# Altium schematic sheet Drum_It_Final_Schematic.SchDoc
size A; SheetNumber: 1; SheetTotal: 1
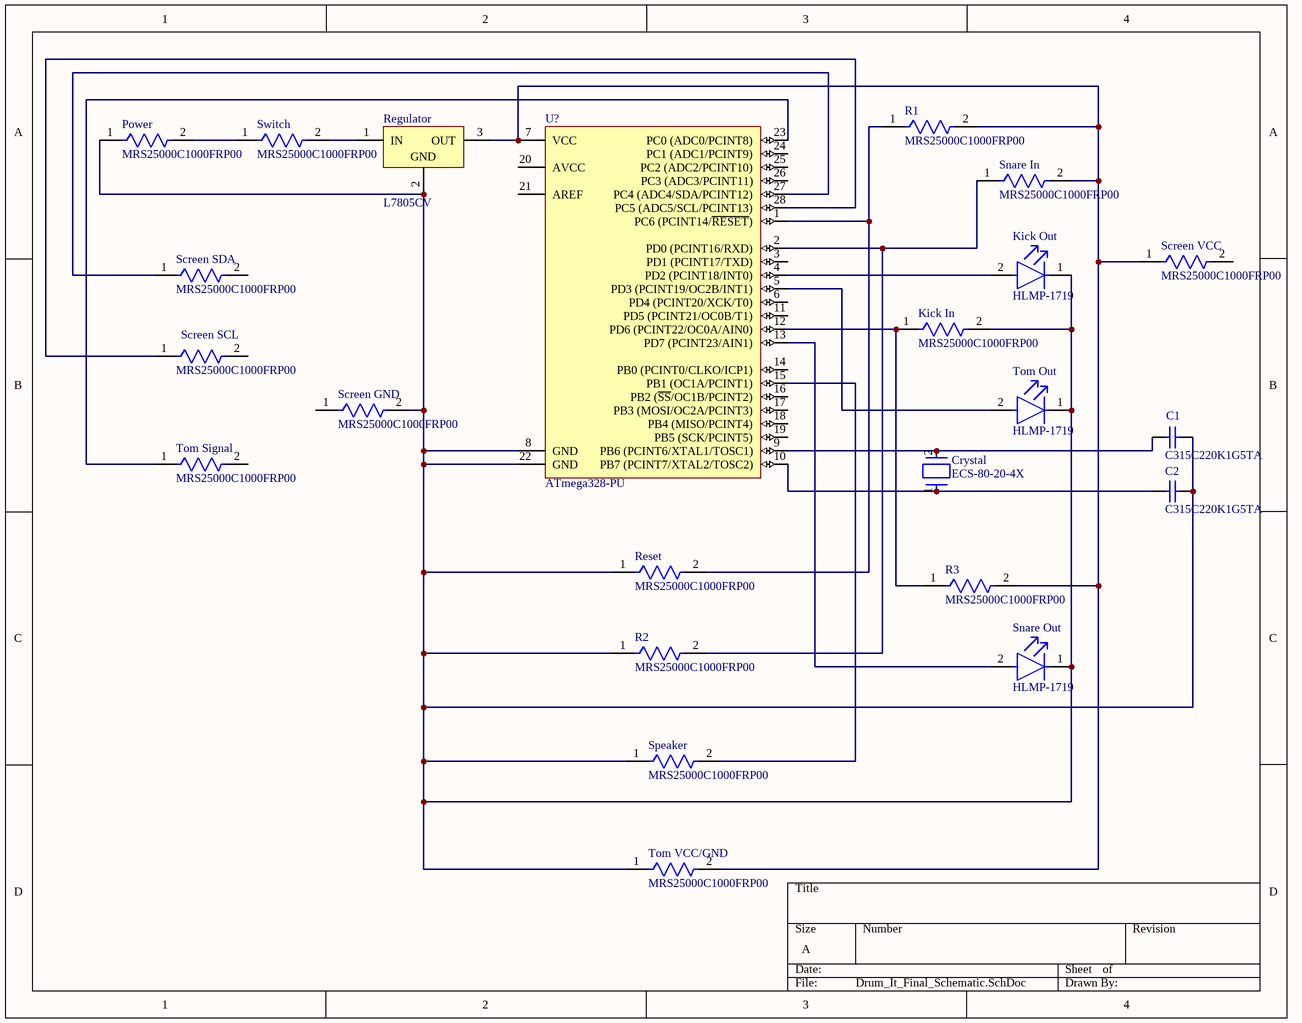
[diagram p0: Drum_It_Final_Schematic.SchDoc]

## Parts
C1  C315C220K1G5TA  [KEMT-C315-THT-2]
C2  C315C220K1G5TA  [KEMT-C315-THT-2]
Crystal  ECS-80-20-4X  [FP-ECS-80-20-4X-MFG]
Kick_In  MRS25000C1000FRP00  [FP-MRS25-MFG]
Kick_Out  HLMP-1719  [FP-HLMP-1719-MFG]
Power  MRS25000C1000FRP00  [FP-MRS25-MFG]
R1  MRS25000C1000FRP00  [FP-MRS25-MFG]
R2  MRS25000C1000FRP00  [FP-MRS25-MFG]
R3  MRS25000C1000FRP00  [FP-MRS25-MFG]
Regulator  L7805CV  [TO220]
Reset  MRS25000C1000FRP00  [FP-MRS25-MFG]
Screen_GND  MRS25000C1000FRP00  [FP-MRS25-MFG]
Screen_SCL  MRS25000C1000FRP00  [FP-MRS25-MFG]
Screen_SDA  MRS25000C1000FRP00  [FP-MRS25-MFG]
Screen_VCC  MRS25000C1000FRP00  [FP-MRS25-MFG]
Snare_In  MRS25000C1000FRP00  [FP-MRS25-MFG]
Snare_Out  HLMP-1719  [FP-HLMP-1719-MFG]
Speaker  MRS25000C1000FRP00  [FP-MRS25-MFG]
Switch  MRS25000C1000FRP00  [FP-MRS25-MFG]
Tom_Out  HLMP-1719  [FP-HLMP-1719-MFG]
Tom_Signal  MRS25000C1000FRP00  [FP-MRS25-MFG]
Tom_VCC/GND  MRS25000C1000FRP00  [FP-MRS25-MFG]
U?  ATmega328-PU  [28P3]

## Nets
NetC1_1: C1.1 Crystal.2 U?.9(PB6_(PCINT6/XTAL1/TOSC1))
NetC1_2: C1.2 C2.2 Kick_In.2 Kick_Out.1(C) Power.1 R2.1 Regulator.2(GND) Reset.1 Screen_GND.2 Snare_Out.1(C) Speaker.1 Tom_Out.1(C) Tom_VCC/GND.1 U?.8(GND) U?.22(GND)
NetC2_1: C2.1 Crystal.1 U?.10(PB7_(PCINT7/XTAL2/TOSC2))
NetKick_In_1: Kick_In.1 R3.1 U?.12(PD6_(PCINT22/OC0A/AIN0))
NetKick_Out_2: Kick_Out.2(A) U?.4(PD2_(PCINT18/INT0))
NetPower_2: Power.2 Switch.1
NetR1_1: R1.1 Reset.2 U?.1(PC6_(PCINT14/~{RESET}))
NetR1_2: R1.2 R3.2 Regulator.3(OUT) Screen_VCC.1 Snare_In.2 Tom_VCC/GND.2 U?.7(VCC)
NetR2_2: R2.2 Snare_In.1 U?.2(PD0_(PCINT16/RXD))
NetRegulator_1: Regulator.1(IN) Switch.2
NetScreen_SCL_1: Screen_SCL.1 U?.28(PC5_(ADC5/SCL/PCINT13))
NetScreen_SDA_1: Screen_SDA.1 U?.27(PC4_(ADC4/SDA/PCINT12))
NetSnare_Out_2: Snare_Out.2(A) U?.13(PD7_(PCINT23/AIN1))
NetSpeaker_2: Speaker.2 U?.15(PB1_(OC1A/PCINT1))
NetTom_Out_2: Tom_Out.2(A) U?.5(PD3_(PCINT19/OC2B/INT1))
NetTom_Signal_1: Tom_Signal.1 U?.23(PC0_(ADC0/PCINT8))

Not connected (* = marked no-connect by the designer): Screen_GND 1; Screen_SCL 2; Screen_SDA 2; Screen_VCC 2; Tom_Signal 2; U? 3(PD1_(PCINT17/TXD)) 6(PD4_(PCINT20/XCK/T0)) 11(PD5_(PCINT21/OC0B/T1)) 14(PB0_(PCINT0/CLKO/ICP1)) 16(PB2_(~{SS}/OC1B/PCINT2)) 17(PB3_(MOSI/OC2A/PCINT3)) 18(PB4_(MISO/PCINT4)) 19(PB5_(SCK/PCINT5)) 20(AVCC) 21(AREF) 24(PC1_(ADC1/PCINT9)) 25(PC2_(ADC2/PCINT10)) 26(PC3_(ADC3/PCINT11))

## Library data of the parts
C1 C2 = CMP-1664-00008-1: Capacitor, Ceramic, 22 pF, +/-10 %, 100 V, -55 to 125 degC, 2-Pin THD, RoHS, Bulk; Max Input Voltage: 40 V; Min Input Voltage: 4.2 V; Output Current: 1.5 A; Output Voltage: 1.2 V; Outputs: 1; Case\Package: TO-220
Crystal = CMP-1669-00002-3: NexarPartId: 316504; Frequency Stability: 50ppm; ESR (Equivalent Series Resistance): 80Ω; Frequency: 8MHz; Tolerance: 0.003%; Load Capacitance: 20pF
Kick_In Power R1-R3 Reset Screen_GND Screen_SCL Screen_SDA Screen_VCC Snare_In Speaker Switch Tom_Signal Tom_VCC/GND = CMP-00030-42757237-1: MRS25000C1000FRP00 Resistor, 100 Ohm, ± 1%, 600 mW, Axial Leaded, Metal Film (Thin Film), Professional; Max Power Dissipation: 600mW; Resistance: 100Ω; Voltage Rating: 350V; Temperature Coefficient: 50ppm/°C; Lead Diameter: 600µm
Kick_Out Snare_Out Tom_Out = CMP-2000-06410-2: LED YELLOW DIFFUSED T-1 T/H; Manufacturer: Broadcom; Wavelength: 585nm; Led Orientation: Straight; Luminous Intensity: 2.1mcd; Forward Voltage: 1.8V; Viewing Angle: 50°; Description: LED Uni-Color Yellow 2-Pin T-1; Reverse Voltage: 5V; Power Dissipation: 17.5mW; Forward Current: 2mA
Regulator = CMP-0244-00483-1: Positive Voltage Regulator, 5V, 3-Pin TO-220
U? = CMP-0095-00015-2: 8-bit AVR Microcontroller, 32KB Flash, 1KB EEPROM, 2KB SRAM, 28-pin PDIP, Industrial Grade (-40°C to 85°C)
